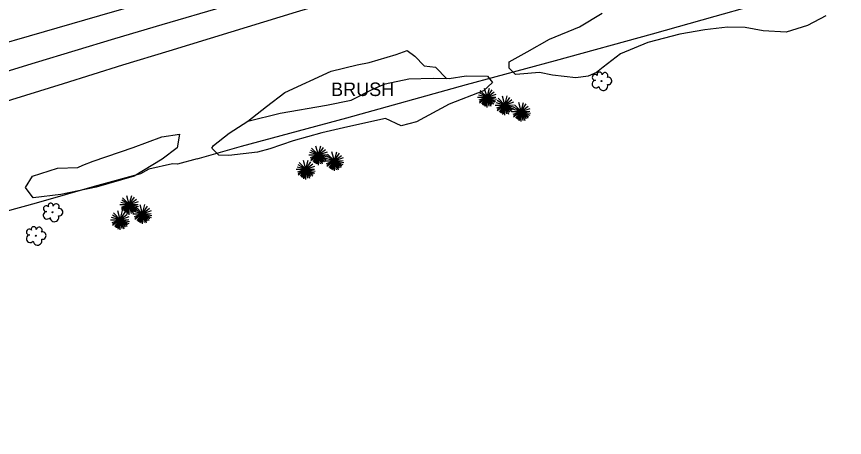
# Model space of a CAD drawing. Extents: x 2129547 to 2134906, y 657330 to 659734.
# Drawn here: x 2133315.8 to 2133745, y 658478.6 to 658697 of the extents above; entities that cross this region are included whole.
import ezdxf

# ---------------------------------------------------------------- set-up
doc = ezdxf.new("R2010")
doc.units = 0
for name, color, linetype in [('PM_X_Edge_Line', 7, 'Continuous'), ('PM_X_Lane_Line', 7, 'Continuous'), ('PV_X_EOP2', 7, 'Continuous'), ('RD_X_Fence', 7, 'Continuous'), ('VG_X_Cells', 7, 'Continuous'), ('VG_X_Shrub_Line_Lt', 7, 'Continuous'), ('VG_X_Text', 7, 'Continuous'), ('VG_X_Tree_Line_Lt', 7, 'Continuous')]:
    doc.layers.add(name, color=color, linetype=linetype)

# ---------------------------------------------------------------- blocks, each defined once
blk = doc.blocks.new('TREE')
at = {"layer": 'VG_X_Cells'}
blk.add_circle((0, 0), 0.00305, dxfattribs=at)
for centre, radius, start, end in [((-0.0125, 0.0428), 0.0167, 354.0047, 205.9741), ((0.0232, 0.0359), 0.0197, 323.83, 165.0376), ((-0.0362, -0.0197), 0.0251, 96.1722, 320.5737), ((-0.042, 0.0237), 0.0187, 39.0625, 279.5412), ((0.0439, 0.0005), 0.0243, 259.1453, 101.4596), ((0.012, -0.0331), 0.029, 184.9476, 19.4572)]:
    blk.add_arc(centre, radius, start, end, dxfattribs=at)
blk = doc.blocks.new('ETREE')
at = {"layer": 'VG_X_Cells'}
for p, q in [((0, 0), (-0.0157, 0.0586)), ((0, 0), (0.016, 0.0597)), ((-0.0627, 0), (0, 0)), ((0, 0), (-0.056, 0.015)), ((0, 0), (-0.0545, -0.0198)), ((0, 0), (-0.0506, -0.029)), ((0, 0), (-0.0496, 0.0292)), ((0, 0), (-0.0496, -0.038)), ((0, 0), (-0.0443, 0.0443)), ((0, 0), (-0.0374, -0.044)), ((0, 0), (-0.0294, -0.051)), ((0, 0), (-0.0211, -0.0551)), ((0, 0), (-0.016, -0.0617)), ((0, 0), (-0.0069, -0.0583)), ((0, 0), (0.0337, 0.0493)), ((0, 0), (0.0464, 0.0356)), ((0, 0), (0.0602, 0.0204)), ((0, 0), (0.0573, 0.0012)), ((0, -0.0665), (0, 0)), ((0, 0), (0.0117, -0.0589)), ((0, 0), (0.0246, -0.0593)), ((0, 0), (0.0322, -0.0482)), ((0, 0), (0.0456, -0.0447)), ((0, 0), (0.0485, -0.0324)), ((0, 0), (0.0567, -0.0247)), ((0, 0), (0.0613, -0.0122))]:
    blk.add_line(p, q, dxfattribs=at)

msp = doc.modelspace()

# ---------------------------------------------------------------- linework, layer by layer
at = {"layer": 'PM_X_Edge_Line'}
for points in [[(2134100.25, 658917.23), (2134063.61, 658906.19), (2134030.5, 658896.13), (2133992.93, 658884.72), (2133952.23, 658872.51), (2133907.65, 658859.14), (2133870.19, 658847.84), (2133822.17, 658833.24), (2133782.71, 658821.22), (2133738.55, 658807.98), (2133692.7, 658794.41), (2133654.59, 658783.4), (2133617.25, 658772.7), (2133577.18, 658761.03), (2133541.61, 658750.79), (2133494, 658737.03), (2133462.99, 658727.98), (2133431.79, 658718.75), (2133387.92, 658705.89), (2133365.27, 658699.28), (2133330.15, 658689.11), (2133297.63, 658679.74)], [(2133300.81, 658650.13), (2133340.17, 658662.31), (2133370.93, 658671.87), (2133394.87, 658679.11), (2133427.09, 658689.08), (2133460.97, 658699.4), (2133496.37, 658710.22), (2133532.31, 658721.07), (2133564.53, 658730.83), (2133600.72, 658741.62), (2133635.89, 658752.26), (2133677.52, 658764.71), (2133710.02, 658774.41), (2133749.64, 658786.47), (2133791.16, 658798.85), (2133827.56, 658809.83), (2133864.21, 658820.91), (2133900.69, 658832.03), (2133931.82, 658841.63), (2133974.36, 658854.66), (2134018.27, 658867.93), (2134054.66, 658878.9), (2134088.9, 658889.31)]]:
    msp.add_lwpolyline(points, dxfattribs=at)
at = {"layer": 'PM_X_Lane_Line'}
msp.add_lwpolyline([(2133285.43, 658660.84), (2133325.6, 658673.06), (2133366.78, 658685.54), (2133391.32, 658692.78), (2133423.26, 658702.17), (2133460.05, 658712.86), (2133499.85, 658724.58), (2133554.8, 658740.88), (2133599.29, 658754.21), (2133636.1, 658765.28), (2133676.03, 658777.16), (2133716.18, 658788.97), (2133754.3, 658800.38), (2133789.1, 658810.81), (2133832.71, 658824.03), (2133874.01, 658836.57), (2133911.3, 658847.78), (2133953.4, 658860.48), (2133993.83, 658872.75), (2134036.36, 658885.82), (2134070.45, 658896.19), (2134110.34, 658908.07)], dxfattribs=at)
at = {"layer": 'PV_X_EOP2'}
msp.add_lwpolyline([(2134100.25, 658917.23), (2134063.61, 658906.19), (2134030.5, 658896.13), (2133992.93, 658884.72), (2133952.23, 658872.51), (2133907.65, 658859.14), (2133870.19, 658847.84), (2133822.17, 658833.24), (2133782.71, 658821.22), (2133738.55, 658807.98), (2133692.7, 658794.41), (2133654.59, 658783.4), (2133617.25, 658772.7), (2133577.18, 658761.03), (2133541.61, 658750.79), (2133494, 658737.03), (2133462.99, 658727.98), (2133431.79, 658718.75), (2133387.92, 658705.89), (2133365.27, 658699.28), (2133330.15, 658689.11), (2133297.63, 658679.74)], dxfattribs=at)
at = {"layer": 'RD_X_Fence'}
for points in [[(2133409.37, 658623.24), (2133432.34, 658629.66), (2133487.07, 658644.47), (2133549.03, 658661.67), (2133595.11, 658674.24), (2133645.48, 658687.97), (2133677.95, 658697.17), (2133733.37, 658712.84), (2133776.67, 658724.79), (2133828.23, 658738.5), (2133881.21, 658752.85), (2133931.92, 658766.78), (2133954.07, 658773.11)], [(2133409.37, 658623.24), (2133399.25, 658620.39), (2133396.55, 658620.65), (2133384.38, 658617.74), (2133380.03, 658615.44), (2133356.03, 658608.88), (2133325.9, 658600.19), (2133292.34, 658590.99), (2133278.32, 658586.5), (2133241.59, 658575.44), (2133201.86, 658562.85), (2133163.22, 658550.3), (2133136.09, 658541.38), (2133085.63, 658525.47), (2133059.75, 658517.07), (2133037.1, 658508.29), (2133014.93, 658496.51), (2132978.92, 658478.61), (2132972.42, 658487.07)]]:
    msp.add_lwpolyline(points, dxfattribs=at)
at = {"layer": 'VG_X_Shrub_Line_Lt'}
msp.add_lwpolyline([(2133435.71, 658642.71), (2133445.38, 658650.38), (2133454.83, 658657.63), (2133478.9, 658668.67), (2133492.28, 658671.89), (2133498.6, 658673.16), (2133512.51, 658677.25), (2133518.36, 658679.38), (2133522.32, 658676.47), (2133527.07, 658671.43), (2133533.05, 658670.65), (2133538.92, 658664.66)], dxfattribs=at)
at = {"layer": 'VG_X_Tree_Line_Lt'}
msp.add_lwpolyline([(2133735.27, 658697.32), (2133725.85, 658692.32), (2133714.82, 658688.84), (2133702.84, 658689.56), (2133693.5, 658691.35), (2133684.31, 658691.52), (2133672.63, 658690.09), (2133659.7, 658687.79), (2133643.02, 658683.58), (2133628.95, 658677.55), (2133619.93, 658670.8), (2133616.42, 658667.95), (2133612.19, 658666.13), (2133605.7, 658665.18), (2133593.58, 658666.58), (2133586.8, 658668.02), (2133576.68, 658667.05), (2133574.36, 658666.93), (2133571.18, 658670.18), (2133571.16, 658673.54), (2133580.45, 658678.63), (2133592.14, 658685.18), (2133607.54, 658691.6), (2133619.35, 658698.8)], dxfattribs=at)
for points in [[(2133507.12, 658644.06), (2133487.45, 658639.82), (2133473.97, 658636.59), (2133459.13, 658632.5), (2133447.01, 658628.26), (2133440.61, 658626.6), (2133425.82, 658624.96), (2133420.7, 658625.08), (2133417.06, 658628.68), (2133417.8, 658630.1), (2133425.91, 658636.54), (2133435.71, 658642.71), (2133452.46, 658646.9), (2133476.53, 658651.02), (2133489.31, 658653.59), (2133500.74, 658659.45), (2133506.85, 658662.12), (2133519.2, 658664.58), (2133531.67, 658665.02), (2133540.08, 658664.86), (2133548.94, 658666.29), (2133559.84, 658666.04), (2133562.56, 658662.68), (2133557.77, 658658.36), (2133539.98, 658651.44), (2133523.06, 658642.43), (2133515.25, 658640.28)], [(2133355.49, 658621.94), (2133376.29, 658629), (2133391.1, 658634.49), (2133400.31, 658636.03), (2133399.08, 658628.81), (2133391.23, 658623.01), (2133376.78, 658614.09), (2133356.97, 658608.49), (2133338.67, 658604.69), (2133324.43, 658602.96), (2133320.38, 658608.26), (2133323.97, 658614.12), (2133337.06, 658618.37), (2133347.48, 658618.7), (2133350.17, 658619.79)]]:
    msp.add_lwpolyline(points, close=True, dxfattribs=at)

# ---------------------------------------------------------------- block references
at = {"layer": 'VG_X_Cells', "xscale": 78.74000000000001, "yscale": 78.74000000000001}
for name, p in [('TREE', (2133619.01, 658663.52)), ('ETREE', (2133559.69, 658655.09)), ('ETREE', (2133568.88, 658651.08)), ('ETREE', (2133577.38, 658647.74)), ('ETREE', (2133472.24, 658625.18)), ('ETREE', (2133480.53, 658622.16)), ('ETREE', (2133465.71, 658617.72)), ('ETREE', (2133374.23, 658599.4)), ('TREE', (2133334.44, 658595.44)), ('ETREE', (2133381.01, 658594.69)), ('ETREE', (2133369.46, 658591.57)), ('TREE', (2133325.69, 658583.28))]:
    msp.add_blockref(name, p, dxfattribs=at)

# ---------------------------------------------------------------- texts
at = {"layer": 'VG_X_Text'}
msp.add_text('BRUSH', height=7, dxfattribs=at).set_placement((2133478.83, 658655.73))

doc.saveas('drawing.dxf')
